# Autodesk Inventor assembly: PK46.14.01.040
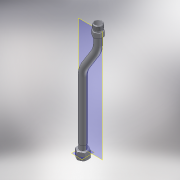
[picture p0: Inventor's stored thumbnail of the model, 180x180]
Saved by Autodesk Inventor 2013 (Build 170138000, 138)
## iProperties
Created: 2005-03
Part Number: PK46.14.01.040
Document SubType Name: Assembly
Designer: elarisa
Manufacturer: Standard
Standards Organization: Custom
Author: elarisa
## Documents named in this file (5)
- C:\Product Design Suite 2013 Test Drive\Model Based Documentation\Workspace\Assemblies\PK46.14.01.040.iam
- C:\Product Design Suite 2013 Test Drive\Model Based Documentation\Workspace\Parts\PK46.14.01.017.ipt
- C:\Product Design Suite 2013 Test Drive\Model Based Documentation\Workspace\Parts\027.03.03.003.ipt
- C:\Product Design Suite 2013 Test Drive\Model Based Documentation\Workspace\Parts\027.07.02.004.ipt
- C:\Product Design Suite 2013 Test Drive\Model Based Documentation\Workspace\Parts\027.08.00.003.ipt
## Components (4 placed, 4 different names)
1. PK46.14.01.017:1 — Insert:3, Insert:2
2. 027.07.02.004:1 — Insert:1, Insert:2
3. 027.08.00.003:1 — Insert:1
4. 027.03.03.003:1 — Insert:3
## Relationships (3: Insert 3)
- Insert:1: 027.07.02.004:1 ↔ 027.08.00.003:1
- Insert:3: PK46.14.01.017:1 ↔ 027.03.03.003:1
- Insert:2: PK46.14.01.017:1 ↔ 027.07.02.004:1
